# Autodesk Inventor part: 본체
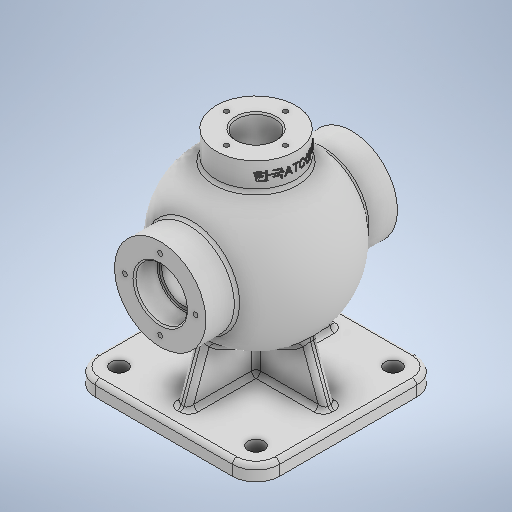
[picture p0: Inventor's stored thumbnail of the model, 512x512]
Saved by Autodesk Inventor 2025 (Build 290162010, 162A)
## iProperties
Created: 2024-07
Part Number: 본체
Material: 일반
Document SubType Name: Modeling
Designer: Admin
Density: 1 g/cm^3
Appearance: 기본값
Author: Admin
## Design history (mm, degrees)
sketch "스케치1"
  geometry: L1 (46.5, 62.5)-(-46.5, 62.5); L2 (-62.5, 46.5)-(-62.5, -46.5); L3 (-46.5, -62.5)-(46.5, -62.5); L4 (62.5, -46.5)-(62.5, 46.5); L5 (62.5, 62.5)-(-62.5, -62.5); L6 (-62.5, 62.5)-(62.5, -62.5); A1 r 16 centre (46.5, -46.5) between (46.5, -62.5) and (62.5, -46.5); A2 r 16 centre (-46.5, -46.5) between (-62.5, -46.5) and (-46.5, -62.5); A3 r 16 centre (-46.5, 46.5) between (-46.5, 62.5) and (-62.5, 46.5); A4 r 16 centre (46.5, 46.5) between (62.5, 46.5) and (46.5, 62.5); 1 further point
  constraints: 12 end point, 8 point on circle, 8 point on line, 8 tangent, 4 centre point, 3 equal radius, 2 midpoint, 2 parallel, 1 horizontal, 1 perpendicular
  dimensions: "d0" = 125 distance of L5.end L6.end; "d1" = 125 distance of L6.end L5.start (= d0); "d2" = 16 radius of A1
extrude "돌출1" new body sketch "스케치1" distance "d3" = 10; taper "d4" = 0 deg
sketch "스케치2"
  geometry: L1 (-50.5, -4)-(50.5, -4); L2 (50.5, -4)-(50.5, 4); L3 (50.5, 4)-(-50.5, 4); L4 (-50.5, 4)-(-50.5, -4); L5 (-50.5, -4)-(50.5, 4); L6 (50.5, -4)-(-50.5, 4); L7 (-4, 50.5)-(4, 50.5); L8 (4, 50.5)-(4, -50.5); L9 (4, -50.5)-(-4, -50.5); L10 (-4, -50.5)-(-4, 50.5); L11 (-4, 50.5)-(4, -50.5); L12 (4, 50.5)-(-4, -50.5); L13 (-62.5, 46.5)-(-62.5, -46.5) reference; L14 (46.5, 62.5)-(-46.5, 62.5) reference; 5 further points
  constraints: 24 end point, 4 midpoint, 4 parallel, 2 horizontal, 2 perpendicular
  dimensions: "d5" = 8 distance of L3.end L1.start; "d6" = 8 distance of L7.start L7.end; "d7" = 12 distance between parallel lines of L13 L4; "d8" = 12 distance between parallel lines of L14 L7
extrude "돌출2" join sketch "스케치2" distance "d9" = 85; taper "d10" = 0 deg
sketch "스케치3"
  geometry: L1 (0, 0)-(46.5, 0) reference; L2 (0, 0)-(0, 85) reference; L3 (46.5, 85)-(0, 85) reference; L4 (46.5, 0)-(46.5, 85) reference; L5 (54.5, 0)-(101, 0) reference; L6 (54.5, 0)-(54.5, 85) reference; L7 (101, 85)-(54.5, 85) reference; L8 (101, 0)-(101, 85) reference; L9 (0, 0)-(30.937, 85); L10 (101, 0)-(70.063, 85); L11 (-12, -10)-(-12, 0) reference; L12 (113, -10)-(113, 0) reference; 1 further point
  constraints: 4 end point, 2 point on line
  dimensions: "d11" = 20 deg angle of L11 L9; "d12" = 20 deg angle of L12 L10
extrude "돌출3" cut sketch "스케치3" stored distance "d13" = 85; taper "d14" = 0 deg
sketch "스케치4"
  geometry: L1 (-54.5, 0)-(-8, 0) reference; L2 (-54.5, 0)-(-54.5, 85) reference; L3 (-8, 85)-(-54.5, 85) reference; L4 (-8, 0)-(-8, 85) reference; L5 (0, 0)-(46.5, 0) reference; L6 (0, 0)-(0, 85) reference; L7 (46.5, 85)-(0, 85) reference; L8 (46.5, 0)-(46.5, 85) reference; L9 (-54.5, 0)-(-23.563, 85); L10 (15.563, 85)-(46.5, 0); L11 (-66.5, -10)-(-66.5, 0) reference; L12 (58.5, -10)-(58.5, 0) reference; 1 further point
  constraints: 4 end point, 2 point on line
  dimensions: "d15" = 20 deg angle of L11 L9; "d16" = 20 deg angle of L12 L10
extrude "돌출4" cut sketch "스케치4" distance "d17" = 10; taper "d18" = 0 deg
sketch "스케치5"
  geometry: L1 (-4, 10)-(-4, 95); L2 (4, 10)-(-4, 10); L3 (4, 95)-(4, 10); L4 (-4, 95)-(4, 95); L5 (0, 0)-(0, 85); C1 r 31 at (0, 85)
  constraints: 4 end point, 1 centre point, 1 coincident, 1 parallel
  dimensions: "d23" = 85 distance of L5.start L5.end; "d24" = 62 diameter of C1
extrude "돌출6" join sketch "스케치5" stored distance "d25" = 130; taper "d26" = 0 deg
sketch "스케치7"
  geometry: L1 (0, 0)-(31, 0); L2 (31, 0)-(85, 0); L3 (85, 0)-(127.511, 0); L4 (139, 0)-(31, 0); A1 r 54 centre (85, 0) between (31, 0) and (139, 0); A2 r 54 centre (85, 0) between (139, 0) and (31, 0); 1 further point
  constraints: 8 end point, 4 point on circle, 3 horizontal, 2 centre point, 1 coincident, 1 collinear, 1 point on line
  dimensions: "d27" = 85 distance of L1.start L2.end; "d28" = 108 diameter of A1
revolve "회전1" sketch "스케치7" stored, may be unused: angle "d29" = 90 deg
node "작업 평면1"
sketch "스케치8"
  geometry: C1 r 27 at (0, 0); 1 further point
  constraints: 1 centre point, 1 coincident
  dimensions: "d31" = 54 diameter of C1
extrude "돌출7" join sketch "스케치8" distance "d32" = 65; taper "d33" = 0 deg
fillet "모깎기1" dims "d34" = 3
fillet "모깎기2" dims "d35" = 3
fillet "모깎기3" dims "d36" = 3
sketch "스케치9"
  geometry: C1 r 31 at (0, 0) reference; 2 further points
  constraints: 1 coincident
hole "구멍1" sketch "스케치9" at (0, 0) diameter "d37" = 35; stored, may be unused: countersink angle "d41" = 90 deg, drill point angle "d43" = 0 deg; dims "d38" = 6, "d39" = 4, "d40" = 2, "d42" = 16
sketch "스케치10"
  geometry: C1 r 31 at (0, 0) reference; 2 further points
  constraints: 1 coincident
hole "구멍2" sketch "스케치10" at (0, 0) diameter "d44" = 35; stored, may be unused: countersink angle "d48" = 90 deg, drill point angle "d50" = 0 deg; dims "d45" = 6, "d46" = 4, "d47" = 2, "d49" = 16
sketch "스케치11"
  geometry: C1 r 17.5 at (0, 0) reference; 2 further points
  constraints: 1 coincident
hole "구멍3" sketch "스케치11" at (0, 0) diameter "d51" = 30; stored, may be unused: countersink angle "d55" = 90 deg, drill point angle "d57" = 0 deg; dims "d52" = 6, "d53" = 4, "d54" = 2, "d56" = 16
fillet "모깎기4" dims "d58" = 0.6
sketch "스케치12"
  geometry: C1 r 27 at (0, 0) reference; 2 further points
  constraints: 1 coincident
hole "구멍4" sketch "스케치12" at (0, 0) diameter "d59" = 26; stored, may be unused: countersink angle "d63" = 90 deg, drill point angle "d65" = 0 deg; dims "d60" = 6, "d61" = 4, "d62" = 2, "d64" = 45
chamfer "모따기1" distance "d66" = 1; stored, may be unused: second distance "d67" = 2, angle "d68" = 45 deg
chamfer "모따기2" distance "d69" = 1; stored, may be unused: second distance "d70" = 2, angle "d71" = 45 deg
chamfer "모따기3" distance "d72" = 1; stored, may be unused: second distance "d73" = 2, angle "d74" = 45 deg
sketch "스케치13"
  geometry: L1 (0, 0)-(0, 129); L2 (0, 129)-(0, 41); L3 (0, 129)-(0, 156.877); C1 r 15 at (0, 85) reference; A1 r 44 centre (0, 85) between (0, 129) and (0, 41); A2 r 44 centre (0, 85) between (0, 41) and (0, 129)
  constraints: 6 end point, 4 point on circle, 2 centre point, 2 vertical, 1 coincident, 1 point on line
  dimensions: "d75" = 88 diameter of A1
revolve "회전2" sketch "스케치13" stored, may be unused: angle "d76" = 90 deg
sketch "스케치14" dims "d81" = 48
  geometry: L1 (0, 0)-(0, 24); C1 r 18.5 at (0, 0) reference; 2 further points
  constraints: 2 coincident, 2 end point, 1 vertical, 1 vertical alignment, 2 other
hole "구멍5" sketch "스케치14" at (0, 24) diameter "d82" = 3.242; stored, may be unused: countersink angle "d86" = 90 deg, drill point angle "d88" = 120 deg; dims "d83" = 12, "d84" = 4, "d85" = 2, "d87" = 15
sketch "스케치15" dims "d92" = 40
  geometry: L1 (0, 0)-(0, 20); 2 further points
  constraints: 2 coincident, 2 end point, 1 vertical, 1 vertical alignment, 2 other
hole "구멍6" sketch "스케치15" at (0, 20) diameter "d93" = 3.242; stored, may be unused: countersink angle "d97" = 90 deg, drill point angle "d99" = 120 deg; dims "d94" = 9, "d95" = 4, "d96" = 2, "d98" = 11
node "작업 평면2"
sketch "스케치16"
  geometry: L1 (0, 0)-(199.962, 0); L2 (150, -27)-(150, 27) reference; 1 further point
  constraints: 2 end point, 1 horizontal, 1 point on line, 1 other
  dimensions: "d104" = 9 distance from line of point (141, 0) L2
feature "엠보싱1" sketch "스케치16" dims "d0" = 125, "d1" = 125 (= d0), "d2" = 16, "d5" = 8, "d7" = 12, "d105" = 0.5, "d106" = 0
sketch "스케치17"
  geometry: A1 r 16 centre (-46.5, 46.5) between (-46.5, 62.5) and (-62.5, 46.5) reference; A2 r 16 centre (-46.5, -46.5) between (-62.5, -46.5) and (-46.5, -62.5) reference; A3 r 16 centre (46.5, -46.5) between (46.5, -62.5) and (62.5, -46.5) reference; A4 r 16 centre (46.5, 46.5) between (62.5, 46.5) and (46.5, 62.5) reference; 5 further points
  constraints: 4 coincident
hole "구멍7" sketch "스케치17" at (-46.5, 46.5), (-46.5, -46.5), (46.5, -46.5), (46.5, 46.5) diameter "d107" = 11; stored, may be unused: countersink angle "d111" = 90 deg, drill point angle "d113" = 0 deg; dims "d108" = 9, "d109" = 4, "d110" = 2, "d112" = 11
node "솔리드1"
pattern_circular "원형 패턴1" dims angle "d90" = 360 deg
mirror "미러1"
pattern_circular "원형 패턴2" dims angle "d101" = 360 deg
node "투영된 루프1"
node "투영된 루프2"
node "투영된 루프3"
node "투영된 루프4"
feature "A9D066F2-1C7D-4E18-AEED-F7BC21143FA4" dims "d37" = 35, "d38" = 6, "d39" = 4, "d40" = 2, "d41" = 90 deg, "d42" = 16, "d43" = 0
other parameters: "d30" = 85, "d77" = 0.5, "d78" = 2, "d79" = 0, "d103" = 327.25
